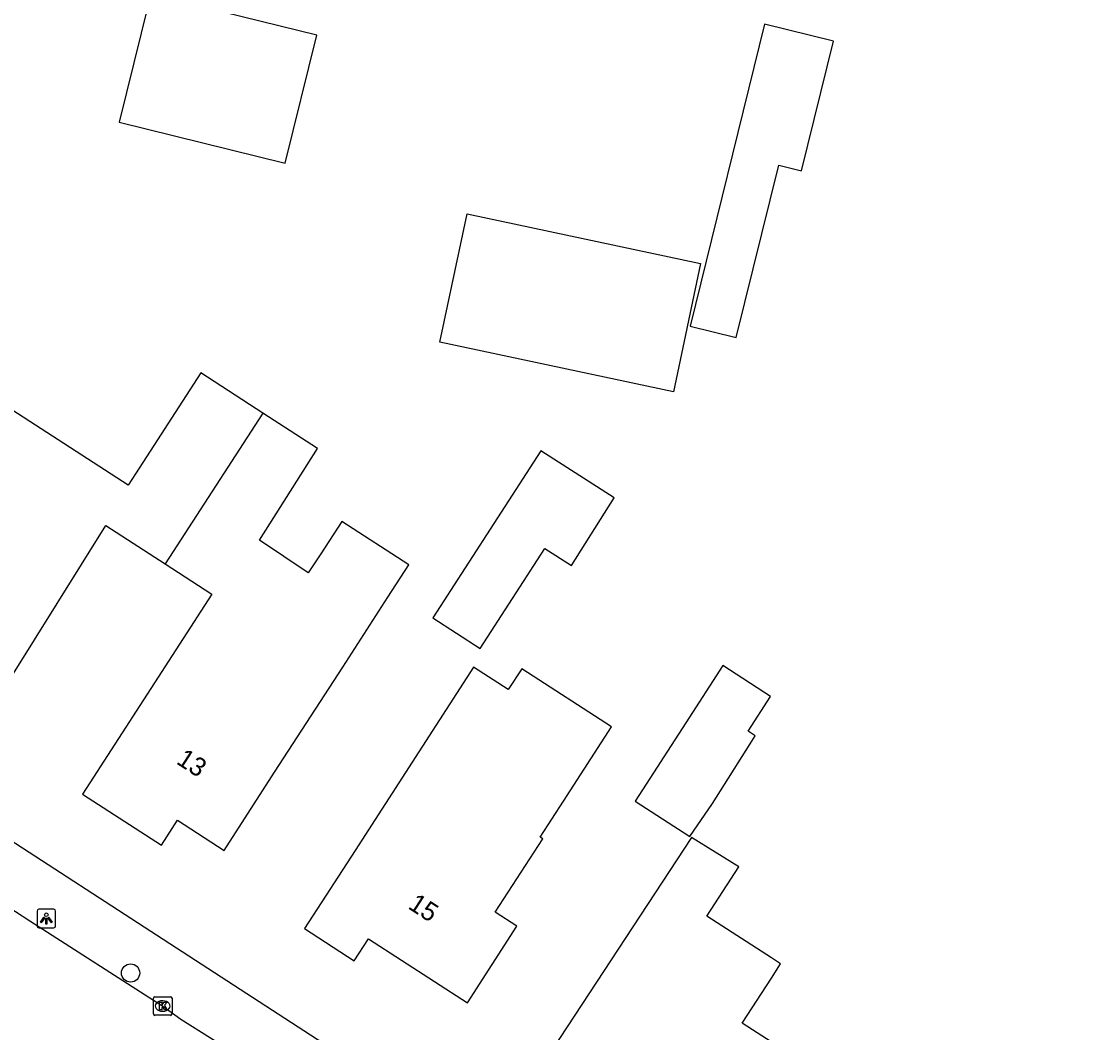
# Model space of a CAD drawing. Extents: x 161141 to 161601, y 381708 to 382245.
# Drawn here: x 161459.7 to 161516.9, y 382072.3 to 382126.6 of the extents above; entities that cross this region are included whole.
import ezdxf

# ---------------------------------------------------------------- set-up
doc = ezdxf.new("R2010")
doc.units = 0
for name, color, linetype in [('IMGEO_Boom', 7, 'Continuous'), ('IMGEO_Kolk', 7, 'Continuous'), ('IMGEO_Lichtpunt', 7, 'Continuous'), ('IMGEO_Pand', 7, 'Continuous'), ('IMGEO_Pand_nummerreeks', 7, 'Continuous'), ('IMGEO_Pand_vergunning_verleend', 7, 'Continuous'), ('IMGEO_Rijbaan_lokaal_open', 7, 'Continuous'), ('IMGEO_Voetpad_open', 7, 'Continuous')]:
    doc.layers.add(name, color=color, linetype=linetype)

msp = doc.modelspace()

# ---------------------------------------------------------------- linework, layer by layer
at = {"layer": 'IMGEO_Boom'}
msp.add_circle((161465.598, 382075.473), 0.489, dxfattribs=at)
at = {"layer": 'IMGEO_Kolk'}
for p, q in [((161466.823, 382073.276), (161466.823, 382074.128)), ((161466.898, 382074.202), (161467.75, 382074.202)), ((161467.311, 382073.982), (161467.336, 382073.982)), ((161467.824, 382074.128), (161467.824, 382073.276)), ((161467.334, 382073.422), (161467.309, 382073.422)), ((161467.75, 382073.202), (161466.898, 382073.202))]:
    msp.add_line(p, q, dxfattribs=at)
for points in [[(161466.823, 382073.276), (161466.823, 382074.128)], [(161466.898, 382074.202), (161467.75, 382074.202)], [(161467.144, 382073.902), (161467.267, 382073.902), (161467.267, 382073.751), (161467.397, 382073.902), (161467.561, 382073.902), (161467.415, 382073.751), (161467.568, 382073.502), (161467.416, 382073.502), (161467.331, 382073.666), (161467.267, 382073.599), (161467.267, 382073.502), (161467.144, 382073.502), (161467.144, 382073.902)], [(161467.824, 382074.128), (161467.824, 382073.276)], [(161467.75, 382073.202), (161466.898, 382073.202)]]:
    msp.add_lwpolyline(points, dxfattribs=at)
for centre, start, end in [((161466.9, 382074.126), 91.552, 178.448), ((161466.9, 382074.126), 91.552, 178.448), ((161467.748, 382074.126), 1.552, 88.448), ((161467.748, 382074.126), 1.552, 88.448), ((161466.9, 382073.278), 181.552, 268.448), ((161466.9, 382073.278), 181.552, 268.448), ((161467.748, 382073.278), 271.552, 358.448), ((161467.748, 382073.278), 271.552, 358.448)]:
    msp.add_arc(centre, 0.0765, start, end, dxfattribs=at)
for centre, major_axis, ratio, start_param, end_param in [((161467.31, 382073.702), (-0.387, 0.002), 0.722429, 4.712389, 7.853982), ((161467.335, 382073.702), (-0.39, 0.002), 0.717154, 1.570796, 4.712389)]:
    msp.add_ellipse(centre, major_axis=major_axis, ratio=ratio, start_param=start_param, end_param=end_param, dxfattribs=at)
at = {"layer": 'IMGEO_Lichtpunt'}
for p, q in [((161460.575, 382078.803), (161460.575, 382077.996)), ((161460.575, 382078.803), (161460.575, 382077.996)), ((161461.477, 382078.898), (161460.669, 382078.898)), ((161461.477, 382078.898), (161460.669, 382078.898)), ((161461.571, 382077.996), (161461.571, 382078.803)), ((161461.571, 382077.996), (161461.571, 382078.803)), ((161460.669, 382077.902), (161461.477, 382077.902)), ((161460.669, 382077.902), (161461.477, 382077.902))]:
    msp.add_line(p, q, dxfattribs=at)
for points in [[(161460.949, 382078.467), (161460.988, 382078.439), (161460.8, 382078.177), (161460.762, 382078.204), (161460.949, 382078.467)], [(161461.051, 382078.419), (161461.098, 382078.419), (161461.098, 382078.097), (161461.051, 382078.097), (161461.051, 382078.419)], [(161461.161, 382078.439), (161461.199, 382078.466), (161461.386, 382078.204), (161461.347, 382078.176), (161461.161, 382078.439)]]:
    msp.add_lwpolyline(points, dxfattribs=at)
msp.add_circle((161461.074, 382078.601), 0.0994, dxfattribs=at)
for centre, start, end in [((161460.669, 382078.803), 90, 180), ((161460.669, 382078.803), 90, 180), ((161461.477, 382078.803), 0, 90), ((161461.477, 382078.803), 0, 90), ((161460.669, 382077.996), 180, 270), ((161460.669, 382077.996), 180, 270), ((161461.477, 382077.996), 270, 0), ((161461.477, 382077.996), 270, 360)]:
    msp.add_arc(centre, 0.0946, start, end, dxfattribs=at)
at = {"layer": 'IMGEO_Pand'}
for points in [[(161467.743, 382132.322), (161464.986, 382121.154), (161473.898, 382118.954), (161475.595, 382125.827), (161469.54, 382127.323)], [(161495.638, 382110.208), (161498.111, 382109.598), (161500.393, 382118.85), (161501.615, 382118.549), (161503.333, 382125.516), (161499.638, 382126.427), (161495.638, 382110.208)], [(161472.701, 382105.54), (161469.366, 382107.698), (161465.469, 382101.675), (161458.914, 382105.916), (161456.737, 382102.518), (161453.857, 382098.067), (161451.141, 382093.869), (161451.95, 382093.346), (161451.901, 382092.38), (161453.687, 382091.225), (161454.573, 382091.678), (161457.833, 382089.569), (161458.989, 382091.357), (161459.126, 382091.268), (161464.273, 382099.499), (161467.455, 382097.44)], [(161467.455, 382097.44), (161469.966, 382095.815), (161463.023, 382085.085), (161467.256, 382082.346), (161468.115, 382083.674), (161470.617, 382082.055), (161473.333, 382086.254), (161476.987, 382091.901), (161479.416, 382095.655), (161480.537, 382097.387), (161476.937, 382099.717), (161475.817, 382097.985), (161475.134, 382096.962), (161472.521, 382098.709), (161475.629, 382103.645), (161472.701, 382105.54)], [(161472.701, 382105.54), (161467.455, 382097.44)], [(161485.305, 382099.915), (161481.828, 382094.542), (161484.363, 382092.902), (161487.84, 382098.275), (161489.276, 382097.346), (161491.559, 382100.981), (161487.621, 382103.505), (161485.305, 382099.915)], [(161485.871, 382090.689), (161484.017, 382091.889), (161480.723, 382086.799), (161477.654, 382082.055), (161474.937, 382077.857), (161477.599, 382076.134), (161478.363, 382077.315), (161483.681, 382073.875), (161486.34, 382077.984), (161485.173, 382078.74), (161487.723, 382082.682), (161487.587, 382082.77), (161488.836, 382084.7), (161491.419, 382088.692), (161486.598, 382091.812), (161485.871, 382090.689)], [(161498.86, 382087.785), (161499.139, 382088.216), (161498.753, 382088.467), (161499.955, 382090.325), (161497.398, 382091.979), (161495.409, 382088.907), (161492.691, 382084.71), (161495.629, 382082.809), (161496.844, 382084.571), (161498.86, 382087.785)], [(161500, 382075.192), (161500.497, 382075.96), (161500, 382076.281), (161496.528, 382078.527), (161498.246, 382081.182), (161495.709, 382082.759), (161487.462, 382070.191), (161489.145, 382069.102), (161488.586, 382068.237), (161491.969, 382066.048), (161492.529, 382066.912), (161494.019, 382065.948), (161495.863, 382068.798), (161499.57, 382066.399), (161502.156, 382070.378), (161498.44, 382072.781), (161500, 382075.192)]]:
    msp.add_lwpolyline(points, dxfattribs=at)
at = {"layer": 'IMGEO_Pand_vergunning_verleend'}
msp.add_lwpolyline([(161496.204, 382113.578), (161494.74, 382106.686), (161482.199, 382109.349), (161483.663, 382116.241), (161496.204, 382113.578)], dxfattribs=at)
at = {"layer": 'IMGEO_Rijbaan_lokaal_open'}
msp.add_lwpolyline([(161385.362, 382126.757), (161388.136, 382124.895), (161391.361, 382122.845), (161399.992, 382117.288), (161403.197, 382115.21), (161416.21, 382106.739), (161420.597, 382103.968), (161426.931, 382099.82), (161440.905, 382090.804), (161444.055, 382088.754), (161453.24, 382082.778), (161460.192, 382078.284), (161467.324, 382073.702), (161468.287, 382073.003), (161471.488, 382070.983), (161480.028, 382065.466), (161483.251, 382063.426), (161485.554, 382061.86), (161494.669, 382055.998), (161498.469, 382053.534), (161512.078, 382044.654), (161521.765, 382038.348), (161525.596, 382035.854)], dxfattribs=at)
at = {"layer": 'IMGEO_Voetpad_open'}
msp.add_lwpolyline([(161523.437, 382040.853), (161500, 382056.07), (161450.498, 382088.211), (161408.789, 382114.947), (161389.855, 382127.317), (161365.175, 382143.293), (161365.084, 382143.565)], dxfattribs=at)

# ---------------------------------------------------------------- texts
at = {"layer": 'IMGEO_Pand_nummerreeks'}
for s, rotation, p in [('13', 327.095, (161468.001, 382086.749)), ('15', 327.1028, (161480.442, 382078.971))]:
    msp.add_text(s, height=1, rotation=rotation, dxfattribs=at).set_placement(p)

doc.saveas('drawing.dxf')
